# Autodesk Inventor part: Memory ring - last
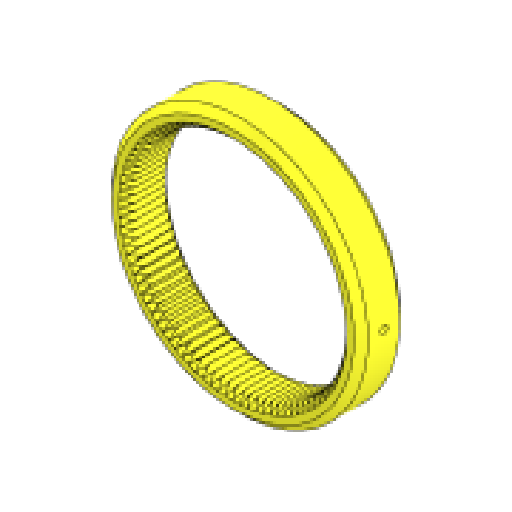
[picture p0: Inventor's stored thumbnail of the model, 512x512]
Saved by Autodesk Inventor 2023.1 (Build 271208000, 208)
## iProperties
Created: 2020-02
Part Number: Memory ring - last
Material: Generic
Document SubType Name: Modeling
Designer: ftrauzettel
Density: 1 g/cm^3
Appearance: Default
Sending System: SolidWorks 2016
Last Author: Pam
Last Saved: 2020-07-17
Author: ftrauzettel
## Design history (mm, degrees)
fillet "Fillet5"
body "Solid1"
